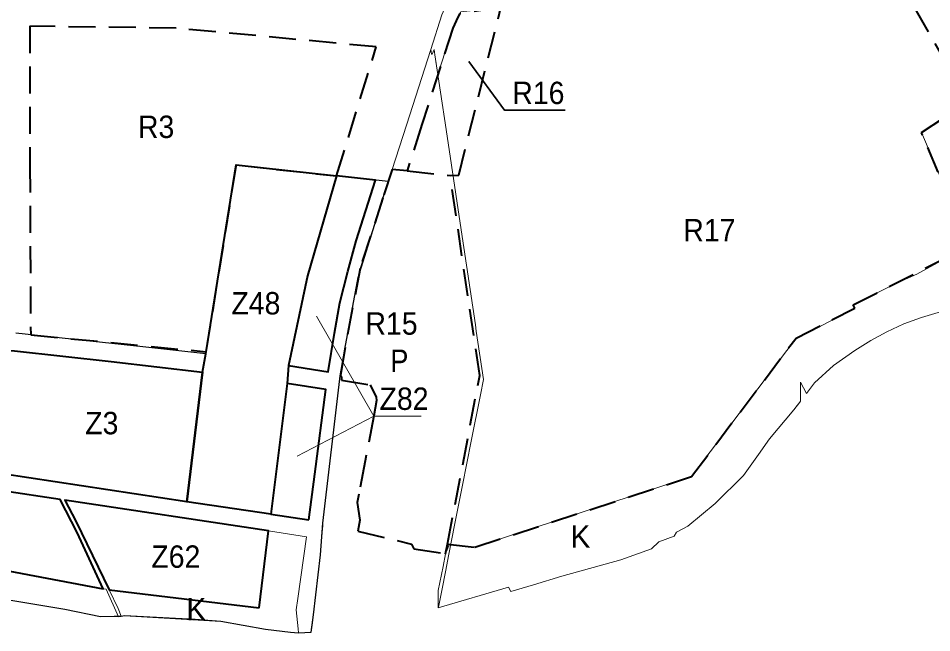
# Model space of a CAD drawing. Extents: x -650276 to -642489, y -1074425 to -1066658.
# Drawn here: x -647044 to -646064, y -1069854 to -1069196 of the extents above; entities that cross this region are included whole.
import ezdxf

# ---------------------------------------------------------------- set-up
doc = ezdxf.new("R2010")
doc.units = 0
doc.header["$LTSCALE"] = 9.6
doc.linetypes.add('MEDIUM_DASHED', pattern=[4.5, 3, -1.5])
for name, color, linetype, lineweight in [('1', 7, 'Continuous', 13), ('42', 7, 'Continuous', 25), ('43', 7, 'Continuous', 13), ('44', 7, 'Continuous', 40), ('45', 7, 'Continuous', 40), ('46', 7, 'Continuous', 13), ('47', 7, 'Continuous', 13), ('60', 7, 'Continuous', 35), ('61', 7, 'MEDIUM_DASHED', 40), ('62', 7, 'Continuous', 35)]:
    doc.layers.add(name, color=color, linetype=linetype, lineweight=lineweight)

msp = doc.modelspace()

# ---------------------------------------------------------------- linework, layer by layer
at = {"layer": '1'}
for points in [[(-646212.43, -1069615.33), (-646238.19, -1069646.63), (-646250, -1069663.09), (-646266.27, -1069685.75), (-646296.64, -1069715.72), (-646325.92, -1069740.05), (-646337.97, -1069746.4), (-646340.48, -1069750.92), (-646357, -1069756.7), (-646364.67, -1069764.23), (-646397.74, -1069776.29), (-646460.97, -1069793.56), (-646491.18, -1069802.78), (-646515.63, -1069810.24), (-646518.19, -1069805.27), (-646593.34, -1069827.68), (-646593.18, -1069826.9), (-646589.29, -1069807.24), (-646585.72, -1069789.16), (-646581.95, -1069770.11), (-646575.83, -1069739.17), (-646567.32, -1069696.19), (-646557.97, -1069648.92), (-646548.14, -1069599.22), (-646544.88, -1069582.73), (-646552.63, -1069530.94), (-646553.61, -1069524.41), (-646568.86, -1069422.54), (-646584.95, -1069314.97), (-646596.95, -1069234.83), (-646597.77, -1069229.37), (-646599.79, -1069234.07), (-646600.68, -1069234.21), (-646601.41, -1069229.34), (-646627.59, -1069310.34), (-646642.89, -1069357.68), (-646652.72, -1069388.08), (-646664.07, -1069423.21), (-646677.18, -1069463.79), (-646679.13, -1069473.51), (-646680.77, -1069481.22), (-646686.56, -1069511.7), (-646693.58, -1069550.28), (-646694.47, -1069556.69), (-646698.4, -1069578.93), (-646698.96, -1069582.26), (-646716.98, -1069736.73), (-646717.19, -1069739.32), (-646717.8, -1069746.68), (-646719.27, -1069764.58), (-646719.79, -1069770.87), (-646727.09, -1069835.05), (-646728.21, -1069843.59), (-646729.54, -1069853.69), (-646743.31, -1069854.26), (-646751.8, -1069853.72), (-646778.74, -1069850.44), (-646826.63, -1069841.84), (-646853.88, -1069839.8), (-646875, -1069838.65), (-646929.67, -1069835.68), (-646933.39, -1069836.51), (-646936.08, -1069837.11), (-646949.48, -1069807.71), (-646952.56, -1069807.13), (-647075.22, -1069784.12)], [(-646017.15, -1069280.19), (-646075.49, -1069318.19), (-646072.33, -1069325.68), (-646071.21, -1069328.33), (-646023.96, -1069440.34)], [(-646020.75, -1069500), (-646075.48, -1069516.38), (-646094.39, -1069523.34), (-646112.56, -1069531.78), (-646129.87, -1069541.19), (-646146.81, -1069551.97), (-646169.9, -1069568.04), (-646190.07, -1069586.48), (-646198.82, -1069597.83), (-646205.25, -1069585.67), (-646205, -1069606.03), (-646205.9, -1069607.17), (-646212.43, -1069615.33)]]:
    msp.add_lwpolyline(points, dxfattribs=at)
at = {"layer": '42'}
msp.add_lwpolyline([(-647060.029, -1069817.854), (-646993.81, -1069829.12), (-646993.81, -1069829.12), (-646955.45, -1069836.93), (-646940.94, -1069836.34), (-646933.39, -1069836.51), (-646929.67, -1069835.68), (-646826.63, -1069841.84), (-646778.74, -1069850.44), (-646751.8, -1069853.72), (-646743.31, -1069854.26), (-646729.54, -1069853.69), (-646727.09, -1069835.05), (-646719.79, -1069770.87), (-646716.98, -1069736.73), (-646698.96, -1069582.26), (-646698.96, -1069582.26), (-646698.4, -1069578.93), (-646693.58, -1069550.28), (-646679.13, -1069473.51), (-646647.141, -1069370.826), (-646702.425, -1069364.771), (-646809.879, -1069353.002), (-646842.103, -1069553.182), (-646842.441, -1069555.283), (-646910.029, -1069548.006), (-646986.633, -1069539.757), (-647046.325, -1069533.275)], dxfattribs=at)
at = {"layer": '44'}
msp.add_line((-646772.907, -1069727.177), (-646732.143, -1069733.308), dxfattribs=at)
msp.add_lwpolyline([(-646660.526, -1069369.36), (-646702.425, -1069364.771), (-646733.74, -1069471.688), (-646754.066, -1069567.993), (-646711.442, -1069574.759), (-646704.68, -1069533.06), (-646699.07, -1069500.57), (-646690.51, -1069466.97), (-646681.5, -1069434.17)], close=True, dxfattribs=at)
at = {"layer": '44', "lineweight": 13}
msp.add_lwpolyline([(-646611.673, -1069622.045), (-646662.372, -1069622.045), (-646744.747, -1069664.938), (-646662.372, -1069622.045), (-646723.996, -1069515.165)], dxfattribs=at)
at = {"layer": '44'}
for points in [[(-646725.82, -1069684.5), (-646714.037, -1069593.585), (-646755.269, -1069587.04), (-646772.907, -1069727.177)], [(-646732.143, -1069733.308), (-646725.82, -1069684.5), (-646725.82, -1069684.5)]]:
    msp.add_lwpolyline(points, dxfattribs=at)
at = {"layer": '45'}
for points in [[(-646842.441, -1069555.283), (-646842.103, -1069553.182), (-646809.879, -1069353.002), (-646702.425, -1069364.771), (-646702.425, -1069364.771), (-646702.425, -1069364.771), (-646702.425, -1069364.771), (-646702.425, -1069364.771), (-646733.74, -1069471.688), (-646733.74, -1069471.688), (-646754.066, -1069567.993)], [(-646842.441, -1069555.283), (-646842.103, -1069553.182), (-646809.879, -1069353.002), (-646702.425, -1069364.771), (-646702.425, -1069364.771), (-646702.425, -1069364.771), (-646702.425, -1069364.771), (-646702.425, -1069364.771), (-646733.74, -1069471.688), (-646733.74, -1069471.688), (-646754.066, -1069567.993)], [(-646754.066, -1069567.993), (-646755.269, -1069587.04), (-646772.906, -1069727.176), (-646863, -1069714), (-646846, -1069575), (-646842.441, -1069555.283)], [(-646754.066, -1069567.993), (-646755.269, -1069587.04), (-646772.906, -1069727.176), (-646863, -1069714), (-646846, -1069575), (-646842.441, -1069555.283)]]:
    msp.add_lwpolyline(points, dxfattribs=at)
for points in [[(-647060.7, -1069683.894), (-647061.304, -1069551.773), (-647047.648, -1069552.245), (-646944.168, -1069563.743), (-646846, -1069575), (-646863, -1069714)], [(-647060.7, -1069683.894), (-647061.304, -1069551.773), (-647047.648, -1069552.245), (-646944.168, -1069563.743), (-646846, -1069575), (-646863, -1069714)], [(-647060.617, -1069702.116), (-647082.682, -1069698.791), (-647089.456, -1069698.579), (-647135.585, -1069697.137), (-647156.782, -1069698.901), (-647154.33, -1069729.69), (-647150.138, -1069782.334), (-647105.334, -1069785.168), (-647082.271, -1069788.81), (-647060.23, -1069786.932), (-646952.56, -1069807.13), (-646980.4, -1069746.98), (-646998.56, -1069711.443)], [(-646785.437, -1069827.534), (-646775.286, -1069745.022), (-646993.771, -1069712.163), (-646981.92, -1069734.86), (-646946.369, -1069808.291)], [(-646785.437, -1069827.534), (-646775.286, -1069745.022), (-646993.771, -1069712.163), (-646981.92, -1069734.86), (-646946.369, -1069808.291)]]:
    msp.add_lwpolyline(points, close=True, dxfattribs=at)
at = {"layer": '47'}
for points in [[(-646593.793, -1069255.911), (-646577.878, -1069206.485), (-646572.586, -1069194.485), (-646569.114, -1069188.86), (-646526.31, -1069184.381), (-646479.84, -1069177.626), (-646250.409, -1069137.52), (-646153.307, -1069059.947), (-646161.484, -1069046.228), (-646256.824, -1069123.414)], [(-646547.412, -1069071.71), (-646549.91, -1069072.542), (-646564.54, -1069125.08), (-646564.605, -1069125.271), (-646574.978, -1069163.017), (-646574.978, -1069163.017), (-646574.33, -1069162.04), (-646575.87, -1069164.54), (-646581.29, -1069173.32), (-646589.56, -1069192.07), (-646601.41, -1069229.34)], [(-646601.41, -1069229.34), (-646600.68, -1069234.21), (-646599.79, -1069234.07), (-646597.77, -1069229.37), (-646596.95, -1069234.83), (-646593.793, -1069255.911)], [(-646023.96, -1069440.34), (-646028.16, -1069441.58), (-646080.35, -1069469.89), (-646102.15, -1069479.49), (-646148.5, -1069503), (-646146.8, -1069506.6), (-646189.17, -1069528.74), (-646209.9, -1069538.5), (-646321.973, -1069686.855), (-646554.262, -1069762.602), (-646581.489, -1069759.421), (-646585.51, -1069769.57)], [(-646491.18, -1069802.78), (-646491.18, -1069802.78), (-646460.97, -1069793.56), (-646397.74, -1069776.29), (-646364.67, -1069764.23), (-646357, -1069756.7), (-646340.48, -1069750.92), (-646337.97, -1069746.4), (-646325.92, -1069740.05), (-646296.64, -1069715.72), (-646266.27, -1069685.75), (-646250, -1069663.09), (-646238.19, -1069646.63), (-646212.43, -1069615.33), (-646210.03, -1069612.42), (-646205.9, -1069607.17), (-646205, -1069606.03), (-646205.25, -1069585.67), (-646198.82, -1069597.83), (-646190.07, -1069586.48), (-646169.9, -1069568.04), (-646146.81, -1069551.97), (-646129.87, -1069541.19), (-646112.56, -1069531.78), (-646094.39, -1069523.34), (-646075.48, -1069516.38), (-646020.75, -1069500)], [(-646778.74, -1069850.44), (-646751.8, -1069853.72), (-646743.31, -1069854.26), (-646743.7, -1069850.07), (-646745.56, -1069829.84), (-646743.85, -1069817.72), (-646734.48, -1069751.35), (-646775.286, -1069745.022), (-646785.437, -1069827.534), (-646946.369, -1069808.291), (-646936.6, -1069828.47), (-646933.39, -1069836.51)], [(-646585.51, -1069769.57), (-646588.25, -1069783.37), (-646593.34, -1069808.99), (-646593.34, -1069827.68)], [(-646593.34, -1069827.68), (-646518.19, -1069805.27), (-646515.63, -1069810.24), (-646491.18, -1069802.78)], [(-646933.39, -1069836.51), (-646933.39, -1069836.51), (-646929.67, -1069835.68), (-646875, -1069838.65), (-646853.88, -1069839.8), (-646826.63, -1069841.84), (-646778.74, -1069850.44), (-646778.74, -1069850.44)]]:
    msp.add_lwpolyline(points, dxfattribs=at)
at = {"layer": '61'}
msp.add_line((-646626.774, -1069359.349), (-646642.89, -1069357.68), dxfattribs=at)
for points in [[(-646583.457, -1069759.191), (-646554.262, -1069762.602), (-646321.973, -1069686.855), (-646209.9, -1069538.5), (-646146.8, -1069506.6), (-646148.5, -1069503), (-646028.16, -1069441.58), (-646023.96, -1069440.34), (-646075.49, -1069318.19), (-646025.14, -1069285.394), (-646153.307, -1069059.947)], [(-646642.89, -1069357.68), (-646652.72, -1069388.08), (-646677.18, -1069463.79), (-646693.58, -1069550.28), (-646698.4, -1069578.93), (-646697.31, -1069579.97), (-646697.31, -1069583.47), (-646666.36, -1069588.57), (-646659.83, -1069601.8), (-646659.52, -1069605.53), (-646662.57, -1069621.66), (-646671.69, -1069669.92), (-646678.52, -1069705.63), (-646680.28, -1069714.83), (-646677.36, -1069733.65), (-646679.46, -1069745.37), (-646622, -1069759.34), (-646619.49, -1069764.46), (-646585.51, -1069769.57), (-646583.457, -1069759.191), (-646548.91, -1069578.56), (-646580.797, -1069364.111)]]:
    msp.add_lwpolyline(points, dxfattribs=at)
for points in [[(-646572.586, -1069194.485), (-646577.878, -1069206.485), (-646611.107, -1069309.68), (-646626.774, -1069359.349), (-646580.797, -1069364.111), (-646571.479, -1069363.822), (-646526.31, -1069184.381), (-646570.296, -1069190.776)], [(-647031.152, -1069204.288), (-647031.152, -1069353.712), (-647030.324, -1069535.053), (-646842.103, -1069553.182), (-646809.879, -1069353.002), (-646702.425, -1069364.771), (-646659.946, -1069226.375), (-646874.542, -1069206.4)]]:
    msp.add_lwpolyline(points, close=True, dxfattribs=at)
at = {"layer": '62'}
msp.add_lwpolyline([(-646457.55, -1069294.294), (-646522.377, -1069294.294), (-646560.609, -1069241.94)], dxfattribs=at)
at = {"layer": '62', "lineweight": 13}
msp.add_lwpolyline([(-646457.55, -1069294.294), (-646522.377, -1069294.294), (-646560.609, -1069241.94)], dxfattribs=at)

# ---------------------------------------------------------------- texts
at = {"layer": '43'}
for p in [(-646451.743, -1069763.13), (-646451.743, -1069763.13), (-646863.536, -1069841.154)]:
    msp.add_text('K', height=24, dxfattribs=at).set_placement(p)
at = {"layer": '44', "width": 0.95}
msp.add_text('Z82', height=24, dxfattribs=at).set_placement((-646656.364, -1069615.463))
at = {"layer": '46', "width": 0.95}
for s, p in [('Z48', (-646815.179, -1069513.185)), ('Z48', (-646815.179, -1069513.185)), ('Z3', (-646971.871, -1069641.589)), ('Z3', (-646971.871, -1069641.589)), ('Z62', (-646900.991, -1069784.684)), ('Z62', (-646900.991, -1069784.684))]:
    msp.add_text(s, height=24, dxfattribs=at).set_placement(p)
at = {"layer": '60', "width": 0.9}
msp.add_text('P', height=24, dxfattribs=at).set_placement((-646644.717, -1069574.793))
msp.add_text('P', height=24, dxfattribs=at).set_placement((-646644.717, -1069574.793))
at = {"layer": '62', "width": 0.95}
for s, p in [('R16', (-646514.063, -1069287.733)), ('R3', (-646915.354, -1069324.087)), ('R3', (-646915.354, -1069324.087)), ('R17', (-646330.736, -1069434.917)), ('R15', (-646671.455, -1069534.875)), ('R15', (-646671.455, -1069534.875))]:
    msp.add_text(s, height=24, dxfattribs=at).set_placement(p)

doc.saveas('drawing.dxf')
